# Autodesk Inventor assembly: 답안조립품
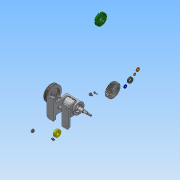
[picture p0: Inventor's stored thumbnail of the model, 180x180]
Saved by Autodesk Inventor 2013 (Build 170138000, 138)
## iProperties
Created: 2016-07
Part Number: 답안조립품
Document SubType Name: Assembly
Designer: mrc
Author: mrc
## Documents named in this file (16)
- C:\Users\mrc\Desktop\460708V1010\답안조립품.iam
- C:\Users\mrc\Desktop\460708V1010\V벨트풀리.ipt
- C:\Users\mrc\Desktop\460708V1010\너트 M 8.ipt
- C:\Users\mrc\Desktop\460708V1010\니플 M 6 x 0.75.ipt
- C:\Users\mrc\Desktop\460708V1010\베어링 15 x 32 x 9.ipt
- C:\Users\mrc\Desktop\460708V1010\본체.ipt
- C:\Users\mrc\Desktop\460708V1010\볼트 M 6 x 8.ipt
- C:\Users\mrc\Desktop\460708V1010\볼트 M4 x 12.ipt
- C:\Users\mrc\Desktop\460708V1010\스퍼기어.ipt
- C:\Users\mrc\Desktop\460708V1010\스프링와셔 8.ipt
- C:\Users\mrc\Desktop\460708V1010\오일 실 15 25 7.ipt
- C:\Users\mrc\Desktop\460708V1010\와셔 6x11.5.ipt
- C:\Users\mrc\Desktop\460708V1010\와셔 8x17.ipt
- C:\Users\mrc\Desktop\460708V1010\축.ipt
- C:\Users\mrc\Desktop\460708V1010\커버.ipt
- C:\Users\mrc\Desktop\460708V1010\키 3 x 3 x 12.ipt
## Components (3 placed, 3 different names)
1. V벨트풀리:1
2. KS B 2023 6002 - 15 x 32 x 9:1
3. ISO 4762 M4 x 12:1
